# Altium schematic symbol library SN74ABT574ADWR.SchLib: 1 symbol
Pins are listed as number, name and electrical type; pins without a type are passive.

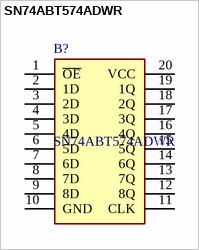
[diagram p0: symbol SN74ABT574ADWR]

## SN74ABT574ADWR
designator B?
Texas Instruments SN74ABT574ADWR, D Type Bus Interface Flip Flop, 3-State, 4.5  5.5 V, 20-Pin SOIC; Geometry.Height: 2.65mm
footprint SOIC127P1030X265-20N
pins: 1 ~{OE}, 2 1D, 3 2D, 4 3D, 5 4D, 6 5D, 7 6D, 8 7D, 9 8D, 10 GND, 11 CLK, 12 8Q, 13 7Q, 14 6Q, 15 5Q, 16 4Q, 17 3Q, 18 2Q, 19 1Q, 20 VCC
